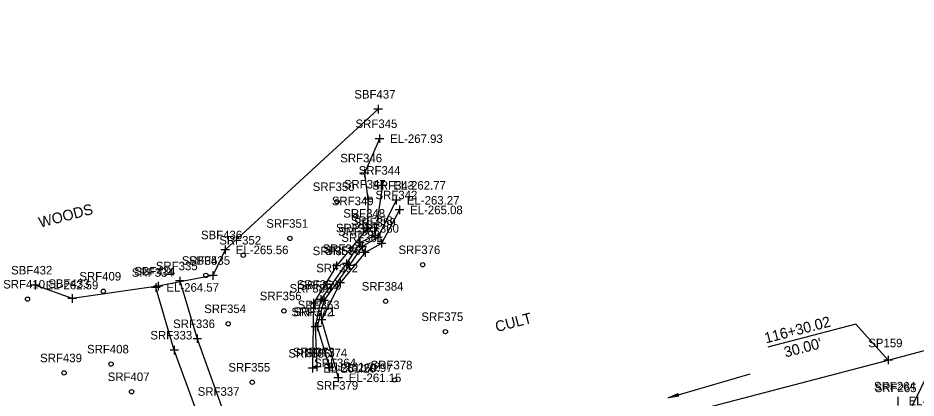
# Model space of a CAD drawing. Extents: x 818717 to 846077, y 440014 to 541392.
# Drawn here: x 832120.6 to 832542, y 493336.2 to 493514.4 of the extents above; entities that cross this region are included whole.
import ezdxf

# ---------------------------------------------------------------- set-up
doc = ezdxf.new("R2010")
doc.units = 0
for name, color, linetype in [('SURVEY - CENTERLINE - Preliminary Text', 7, 'Continuous'), ('SURVEY - DRAINAGE - Natural Features Text', 7, 'Continuous'), ('SURVEY - DTM - Breaklines', 7, 'Continuous'), ('SURVEY - DTM - Breaklines - Points - Elevations', 7, 'Continuous'), ('SURVEY - DTM - Breaklines - Points - Locators', 7, 'Continuous'), ('SURVEY - DTM - Breaklines - Points - Numbers', 7, 'Continuous'), ('SURVEY - DTM - Spot Points - Locators', 7, 'Continuous'), ('SURVEY - DTM - Spot Points - Point Numbers', 7, 'Continuous'), ('SURVEY - PROPERTY - ROW Lines', 7, 'Continuous'), ('SURVEY - PROPERTY - ROW Lines - Points - Locators', 7, 'Continuous'), ('SURVEY - PROPERTY - ROW Lines - Points - Numbers', 7, 'Continuous'), ('SURVEY - PROPERTY - Station and Offset Flags', 7, 'Continuous'), ('SURVEY - TRAFFIC CONTROL - Pavement Marking - Points - Numbers', 7, 'Continuous'), ('SURVEY - TRANSPORTATION - Features', 7, 'Continuous'), ('SURVEY - TRANSPORTATION - Features - Points - Elevations', 7, 'Continuous'), ('SURVEY - TRANSPORTATION - Features - Points - Locators', 7, 'Continuous'), ('SURVEY - TRANSPORTATION - Features - Points - Numbers', 7, 'Continuous'), ('SURVEY - TRANSPORTATION - Roads - Points - Elevations', 7, 'Continuous'), ('SURVEY - TRANSPORTATION - Roads - Points - Locators', 7, 'Continuous'), ('SURVEY - TRANSPORTATION - Roads - Points - Numbers', 7, 'Continuous'), ('SURVEY - VEGETATION - Features - Points - Elevations', 7, 'Continuous'), ('SURVEY - VEGETATION - Features - Points - Locators', 7, 'Continuous'), ('SURVEY - VEGETATION - Features - Points - Numbers', 7, 'Continuous'), ('SURVEY - VEGETATION - Features with Text', 7, 'Continuous')]:
    doc.layers.add(name, color=color, linetype=linetype)

msp = doc.modelspace()

# ---------------------------------------------------------------- linework, layer by layer
at = {"layer": 'SURVEY - CENTERLINE - Preliminary Text'}
msp.add_line((832536.48, 493325), (832577.8, 493408.74), dxfattribs=at)
at = {"layer": 'SURVEY - DRAINAGE - Natural Features Text'}
for p, q in [((832425.69, 493336.28), (832464.11, 493347.58)), ((832428.28, 493337.05), (832425.69, 493336.28))]:
    msp.add_line(p, q, dxfattribs=at)
msp.add_lwpolyline([(832425.69, 493336.28), (832430.35, 493338.33), (832429.91, 493337.53), (832430.72, 493337.08)], close=True, dxfattribs=at)
msp.add_lwpolyline([(832425.69, 493336.28), (832430.35, 493338.33), (832429.91, 493337.53), (832430.72, 493337.08), (832425.69, 493336.28)], dxfattribs=at)
at = {"layer": 'SURVEY - DTM - Breaklines'}
for points in [[(832290.24, 493457.78), (832283.18, 493441.7), (832284.76, 493429.45), (832284.54, 493415.77), (832270.12, 493398.2), (832259.27, 493380.63), (832258.84, 493350.14)], [(832291.71, 493435.92), (832288.1, 493412.35), (832281.05, 493408.89), (832274.83, 493399.21), (832262.69, 493382.43), (832260.12, 493369.52), (832260.87, 493350.8)], [(832298.09, 493428.9), (832289.48, 493411.52), (832282.12, 493407.29), (832276.04, 493398.3), (832264.08, 493381.97), (832260.97, 493369.73), (832266.72, 493350.38)], [(832299.61, 493424.4), (832291.14, 493408.72), (832283.47, 493404.42), (832271.79, 493390.14), (832263.09, 493372.89), (832270.82, 493345.68)]]:
    msp.add_lwpolyline(points, dxfattribs=at)
at = {"layer": 'SURVEY - DTM - Breaklines - Points - Locators'}
for p, q in [((832290.24, 493459.78), (832290.24, 493455.78)), ((832292.24, 493457.78), (832288.24, 493457.78)), ((832283.18, 493443.7), (832283.18, 493439.7)), ((832285.18, 493441.7), (832281.18, 493441.7)), ((832293.71, 493435.92), (832289.71, 493435.92)), ((832291.71, 493437.92), (832291.71, 493433.92)), ((832284.76, 493431.45), (832284.76, 493427.45)), ((832298.09, 493430.9), (832298.09, 493426.9)), ((832286.76, 493429.45), (832282.76, 493429.45)), ((832300.09, 493428.9), (832296.09, 493428.9)), ((832299.61, 493426.4), (832299.61, 493422.4)), ((832301.61, 493424.4), (832297.61, 493424.4)), ((832284.54, 493417.77), (832284.54, 493413.77)), ((832286.54, 493415.77), (832282.54, 493415.77)), ((832288.1, 493414.35), (832288.1, 493410.35)), ((832289.48, 493413.52), (832289.48, 493409.52)), ((832283.05, 493408.89), (832279.05, 493408.89)), ((832281.05, 493410.89), (832281.05, 493406.89)), ((832282.12, 493409.29), (832282.12, 493405.29)), ((832290.1, 493412.35), (832286.1, 493412.35)), ((832291.48, 493411.52), (832287.48, 493411.52)), ((832293.14, 493408.72), (832289.14, 493408.72)), ((832291.14, 493410.72), (832291.14, 493406.72)), ((832284.12, 493407.29), (832280.12, 493407.29)), ((832285.47, 493404.42), (832281.47, 493404.42)), ((832283.47, 493406.42), (832283.47, 493402.42)), ((832270.12, 493400.2), (832270.12, 493396.2)), ((832274.83, 493401.21), (832274.83, 493397.21)), ((832276.04, 493400.3), (832276.04, 493396.3)), ((832272.12, 493398.2), (832268.12, 493398.2)), ((832276.83, 493399.21), (832272.83, 493399.21)), ((832278.04, 493398.3), (832274.04, 493398.3)), ((832271.79, 493392.14), (832271.79, 493388.14)), ((832273.79, 493390.14), (832269.79, 493390.14)), ((832262.69, 493384.43), (832262.69, 493380.43)), ((832264.08, 493383.97), (832264.08, 493379.97)), ((832261.27, 493380.63), (832257.27, 493380.63)), ((832259.27, 493382.63), (832259.27, 493378.63)), ((832264.69, 493382.43), (832260.69, 493382.43)), ((832266.08, 493381.97), (832262.08, 493381.97)), ((832263.09, 493374.89), (832263.09, 493370.89)), ((832260.12, 493371.52), (832260.12, 493367.52)), ((832260.97, 493371.73), (832260.97, 493367.73)), ((832265.09, 493372.89), (832261.09, 493372.89)), ((832262.12, 493369.52), (832258.12, 493369.52)), ((832262.97, 493369.73), (832258.97, 493369.73)), ((832260.84, 493350.14), (832256.84, 493350.14)), ((832258.84, 493352.14), (832258.84, 493348.14)), ((832262.87, 493350.8), (832258.87, 493350.8)), ((832260.87, 493352.8), (832260.87, 493348.8)), ((832268.72, 493350.38), (832264.72, 493350.38)), ((832266.72, 493352.38), (832266.72, 493348.38)), ((832272.82, 493345.68), (832268.82, 493345.68)), ((832270.82, 493347.68), (832270.82, 493343.68))]:
    msp.add_line(p, q, dxfattribs=at)
at = {"layer": 'SURVEY - DTM - Spot Points - Locators'}
for centre in [(832270.34, 493428.26), (832279.14, 493421.6), (832248.2, 493411.03), (832226.3, 493403.16), (832310.51, 493398.7), (832208.75, 493393.68), (832125.08, 493382.56), (832160.64, 493386.28), (832293.12, 493381.56), (832245.41, 493377.06), (832219.24, 493371.02), (832321.16, 493367.31), (832164.28, 493352.12), (832142.24, 493347.98), (832297.36, 493344.66), (832230.55, 493343.61), (832173.92, 493339.16)]:
    msp.add_circle(centre, 1, dxfattribs=at)
at = {"layer": 'SURVEY - PROPERTY - ROW Lines'}
for p, q in [((832528.9, 493354.02), (833177.35, 493523.36)), ((832170.25, 493260.36), (832528.9, 493354.02))]:
    msp.add_line(p, q, dxfattribs=at)
at = {"layer": 'SURVEY - PROPERTY - ROW Lines - Points - Locators'}
for p, q in [((832530.9, 493354.02), (832526.9, 493354.02)), ((832528.9, 493356.02), (832528.9, 493352.02))]:
    msp.add_line(p, q, dxfattribs=at)
at = {"layer": 'SURVEY - PROPERTY - Station and Offset Flags'}
msp.add_line((832513.83, 493370.89), (832472.47, 493360.09), dxfattribs=at)
msp.add_lwpolyline([(832513.83, 493370.89), (832528.9, 493354.02)], dxfattribs=at)
at = {"layer": 'SURVEY - TRANSPORTATION - Features'}
for points in [[(832223.17, 493253.67), (832226.49, 493262.95), (832226.4, 493267.01), (832226.48, 493271.98), (832209.7, 493315.68), (832193.96, 493358.65), (832185.25, 493388.05)], [(832196.53, 493391.1), (832204.75, 493364), (832216.16, 493332.26), (832230.23, 493299.2), (832241.3, 493272.28), (832244.2, 493265.69), (832251.05, 493261.07)]]:
    msp.add_lwpolyline(points, dxfattribs=at)
at = {"layer": 'SURVEY - TRANSPORTATION - Features - Points - Locators'}
for p, q in [((832196.53, 493393.1), (832196.53, 493389.1)), ((832187.25, 493388.05), (832183.25, 493388.05)), ((832185.25, 493390.05), (832185.25, 493386.05)), ((832198.53, 493391.1), (832194.53, 493391.1)), ((832206.75, 493364), (832202.75, 493364)), ((832204.75, 493366), (832204.75, 493362)), ((832195.96, 493358.65), (832191.96, 493358.65)), ((832193.96, 493360.65), (832193.96, 493356.65))]:
    msp.add_line(p, q, dxfattribs=at)
at = {"layer": 'SURVEY - TRANSPORTATION - Roads - Points - Locators'}
msp.add_line((832533.51, 493336.77), (832533.51, 493332.77), dxfattribs=at)
at = {"layer": 'SURVEY - VEGETATION - Features - Points - Locators'}
for p, q in [((832289.66, 493473.61), (832289.66, 493469.61)), ((832291.66, 493471.61), (832287.66, 493471.61)), ((832219.82, 493405.65), (832215.82, 493405.65)), ((832217.82, 493407.65), (832217.82, 493403.65)), ((832214.04, 493393.68), (832210.04, 493393.68)), ((832212.04, 493395.68), (832212.04, 493391.68)), ((832130.61, 493389.14), (832126.61, 493389.14)), ((832128.61, 493391.14), (832128.61, 493387.14)), ((832188.39, 493388.67), (832184.39, 493388.67)), ((832186.39, 493390.67), (832186.39, 493386.67)), ((832146.05, 493384.83), (832146.05, 493380.83)), ((832148.05, 493382.83), (832144.05, 493382.83))]:
    msp.add_line(p, q, dxfattribs=at)
at = {"layer": 'SURVEY - VEGETATION - Features with Text'}
msp.add_lwpolyline([(832289.66, 493471.61), (832217.82, 493405.65), (832212.04, 493393.68), (832186.39, 493388.67), (832146.05, 493382.83), (832128.61, 493389.14)], dxfattribs=at)

# ---------------------------------------------------------------- texts
at = {"layer": 'SURVEY - DTM - Breaklines - Points - Elevations'}
for s, p in [('EL-267.93', (832295.24, 493455.78)), ('EL-262.77', (832296.71, 493433.92)), ('EL-263.27', (832303.09, 493426.9)), ('EL-265.08', (832304.61, 493422.4)), ('EL-261.20', (832263.84, 493348.14)), ('EL-261.22', (832265.87, 493348.8)), ('EL-260.97', (832271.72, 493348.38)), ('EL-261.15', (832275.82, 493343.68))]:
    msp.add_text(s, height=4, dxfattribs=at).set_placement(p)
at = {"layer": 'SURVEY - DTM - Breaklines - Points - Numbers'}
for s, p in [('SRF345', (832279, 493462.78)), ('SRF346', (832271.83, 493446.7)), ('SRF344', (832280.47, 493440.92)), ('SRF347', (832273.52, 493434.45)), ('SRF343', (832286.85, 493433.9)), ('SRF342', (832288.37, 493429.4)), ('SRF348', (832273.25, 493420.77)), ('SRF358', (832276.81, 493417.35)), ('SRF365', (832269.81, 493413.89)), ('SRF359', (832278.23, 493416.52)), ('SRF360', (832279.73, 493413.72)), ('SRF366', (832270.77, 493412.29)), ('SRF361', (832272.38, 493409.42)), ('SRF357', (832258.88, 493403.2)), ('SRF368', (832263.54, 493404.21)), ('SRF367', (832264.8, 493403.3)), ('SRF362', (832260.55, 493395.14)), ('SRF385', (832248.03, 493385.63)), ('SRF369', (832251.43, 493387.43)), ('SRF370', (832252.66, 493386.97)), ('SRF363', (832251.85, 493377.89)), ('SRF372', (832248.88, 493374.52)), ('SRF371', (832249.89, 493374.73)), ('SRF386', (832247.49, 493355.14)), ('SRF373', (832249.63, 493355.8)), ('SRF374', (832255.48, 493355.38)), ('SRF364', (832259.58, 493350.68))]:
    msp.add_text(s, height=4, dxfattribs=at).set_placement(p)
at = {"layer": 'SURVEY - DTM - Spot Points - Point Numbers'}
for s, p in [('SRF350', (832258.93, 493433.26)), ('SRF349', (832267.89, 493426.6)), ('SRF351', (832237.12, 493416.03)), ('SRF352', (832215.06, 493408.16)), ('SRF376', (832299.16, 493403.7)), ('SRF353', (832197.51, 493398.68)), ('SRF409', (832149.39, 493391.28)), ('SRF410', (832113.66, 493387.56)), ('SRF384', (832281.88, 493386.56)), ('SRF356', (832234.06, 493382.06)), ('SRF354', (832208, 493376.02)), ('SRF375', (832309.92, 493372.31)), ('SRF408', (832152.99, 493357.12)), ('SRF439', (832130.99, 493352.98)), ('SRF355', (832219.31, 493348.61)), ('SRF378', (832286.07, 493349.66)), ('SRF407', (832162.68, 493344.16)), ('SRF379', (832260.61, 493340.12))]:
    msp.add_text(s, height=4, dxfattribs=at).set_placement(p)
at = {"layer": 'SURVEY - PROPERTY - ROW Lines - Points - Numbers'}
msp.add_text('SP159', height=4, dxfattribs=at).set_placement((832519.59, 493360.02))
at = {"layer": 'SURVEY - PROPERTY - Station and Offset Flags'}
for s, p in [('116+30.02', (832471.58, 493361.79)), ("30.00'", (832480.8, 493355.16))]:
    msp.add_text(s, height=5, rotation=14.6355, dxfattribs=at).set_placement(p)
at = {"layer": 'SURVEY - TRAFFIC CONTROL - Pavement Marking - Points - Numbers'}
msp.add_text('SRF265', height=4, dxfattribs=at).set_placement((832522.62, 493338.96))
at = {"layer": 'SURVEY - TRANSPORTATION - Features - Points - Elevations'}
msp.add_text('EL-264.57', height=4, dxfattribs=at).set_placement((832190.25, 493386.05))
at = {"layer": 'SURVEY - TRANSPORTATION - Features - Points - Numbers'}
for s, p in [('SRF335', (832185.29, 493396.1)), ('SRF334', (832174.01, 493393.05)), ('SRF336', (832193.4, 493369)), ('SRF333', (832182.72, 493363.65)), ('SRF337', (832204.92, 493337.26))]:
    msp.add_text(s, height=4, dxfattribs=at).set_placement(p)
at = {"layer": 'SURVEY - TRANSPORTATION - Roads - Points - Elevations'}
msp.add_text('EL-261.42', height=4, dxfattribs=at).set_placement((832538.51, 493332.77))
at = {"layer": 'SURVEY - TRANSPORTATION - Roads - Points - Numbers'}
msp.add_text('SRF264', height=4, dxfattribs=at).set_placement((832522.27, 493339.77))
at = {"layer": 'SURVEY - VEGETATION - Features - Points - Elevations'}
for s, p in [('EL-265.56', (832222.82, 493403.65)), ('EL-262.59', (832133.61, 493387.14))]:
    msp.add_text(s, height=4, dxfattribs=at).set_placement(p)
at = {"layer": 'SURVEY - VEGETATION - Features - Points - Numbers'}
for s, p in [('SBF437', (832278.42, 493476.61)), ('SBF436', (832206.47, 493410.65)), ('SBF435', (832200.8, 493398.68)), ('SBF432', (832117.37, 493394.14)), ('SBF434', (832175.15, 493393.67)), ('SBF433', (832134.82, 493387.83))]:
    msp.add_text(s, height=4, dxfattribs=at).set_placement(p)
at = {"layer": 'SURVEY - VEGETATION - Features with Text'}
for s, p in [('WOODS', (832131.04, 493416)), ('CULT', (832345.28, 493367.08))]:
    msp.add_text(s, height=5, rotation=14.6355, dxfattribs=at).set_placement(p)

doc.saveas('drawing.dxf')
